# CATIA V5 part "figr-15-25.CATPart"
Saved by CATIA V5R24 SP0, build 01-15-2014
Part number: Part1
Bounding box of the stored display mesh (mm): x -50 to 50, y -25 to 26, z -24 to 1
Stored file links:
  D:\KAVITA\CATIA V5-6R2014 Project_ Kavita\CATIA V5-6R2014_partfiles\Partfiles\c15_catia_v5-6r2014_prt\figr-15-25.CATPart
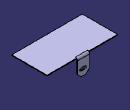
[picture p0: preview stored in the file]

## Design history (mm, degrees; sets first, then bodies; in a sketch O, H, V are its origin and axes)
SheetMetalParameters1: Thickness 1, BendRadius 2, KFactor 0.400515 {= log(min(100,max(20*SheetMetalParameters1.BendRadius,SheetMetalParameters1.Thickness)/SheetMetalParameters1.Thickness))/log(100)/2}, ReliefRadialLength 1, ReliefAxialLength 2, MinimumBendRadius 0
Body1 (main body)
  Sketch1 on xy-plane, origin (0, 0, 0), H (1, 0, 0), V (0, 1, 0)
    line L1 (-50, 25) -> (50, 25)
    line L2 (50, 25) -> (50, -25)
    line L3 (50, -25) -> (-50, -25)
    line L4 (-50, -25) -> (-50, 25)
    length L1 = 100
    distance V L2 = 50
    length L2 = 50
    distance H L3 = 25
    horizontal: L1 H, L3 H
    vertical: L2 V, L4 V
  Wall1: Thickness 1, Profile Sketch1
  Sketch2 on face of Wall1, origin (50, 25, 0), H (-1, 0, 0), V (0, 0, 1)
    line L1 (42.3549, 1) -> (42.3549, -19)
    point P2 (42.3549, -19)
    line L2 (42.3549, -19) -> (47.3549, -24)
    point P3 (47.3549, -24)
    line L3 (47.3549, -24) -> (54.3549, -24)
    point P4 (54.3549, -24)
    line L4 (54.3549, -24) -> (59.3549, -19)
    point P5 (59.3549, -19)
    line L5 (59.3549, -19) -> (59.3549, 1)
    line L6 (59.3549, 1) -> (42.3549, 1)
    reference projected line E1 (100, 1) -> (0, 1) from edge [face of Wall1 | face of Wall1]
    ellipse A1 centre (50.1164, -15.2153) semi-axes 5.0583, 2.1402 rotation 0
    length L5 = 20
    length L1 = 20
    length L3 = 7
    distance P4 L5 = 5
    distance P2 P3 H = 5
    distance L3 P5 = 5
    vertical: L1 V, L5 V
    horizontal: L3 H, L6 H
    coincidence: L6 E1
    parallelism: A1 L3
  d_NewWallOnEdge1: NewWallOnEdge_Edge edge [face of Wall1 | face of Wall1], NewWallOnEdge_WallProfile Sketch2, NewWallOnEdge_Length 100, NewWallOnEdge_HeightLimitOffset 0, NewWallOnEdge_WidthOffset1 0, NewWallOnEdge_WidthOffset2 0, NewWallOnEdge_Angle 0, NewWallOnEdge_BendRadiusValue 2 {= SheetMetalParameters1.BendRadius}, NewWallOnEdge_BendTable SheetMetalParameters1, KFacteur 0.400515 {= log(min(100,max(20*d_NewWallOnEdge1.Radius,SheetMetalParameters1.Thickness)/SheetMetalParameters1.Thickness))/log(100)/2}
